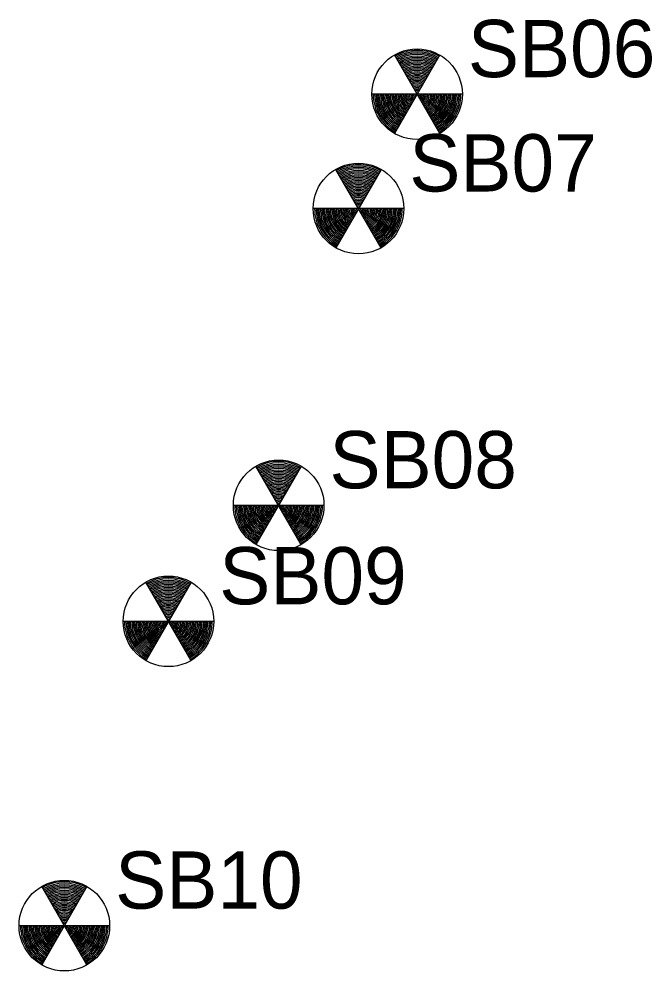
# Model space of a CAD drawing. Extents: x 557444 to 557718, y 506539 to 506965.
# Drawn here: x 557443.9 to 557488.1, y 506539.5 to 506606 of the extents above; entities that cross this region are included whole.
import ezdxf

# ---------------------------------------------------------------- set-up
doc = ezdxf.new("R2010")
doc.units = 0
doc.layers.add('Exist Roads EOP Cogo Point CELL', color=7, linetype='Continuous')

msp = doc.modelspace()

# ---------------------------------------------------------------- linework, layer by layer
at = {"layer": 'Exist Roads EOP Cogo Point CELL'}
for p, q in [((557473.295, 506597.967), (557470.133, 506603.444)), ((557473.295, 506603.444), (557470.133, 506597.967)), ((557474.876, 506600.706), (557468.552, 506600.706)), ((557469.203, 506589.983), (557466.041, 506595.46)), ((557469.203, 506595.46), (557466.041, 506589.983)), ((557470.784, 506592.722), (557464.46, 506592.722)), ((557463.63, 506569.258), (557460.468, 506574.735)), ((557463.63, 506574.735), (557460.468, 506569.258)), ((557465.211, 506571.997), (557458.887, 506571.997)), ((557455.935, 506561.159), (557452.773, 506566.635)), ((557455.935, 506566.635), (557452.773, 506561.159)), ((557457.516, 506563.897), (557451.192, 506563.897)), ((557448.668, 506539.909), (557445.506, 506545.386)), ((557448.668, 506545.386), (557445.506, 506539.909)), ((557450.249, 506542.648), (557443.925, 506542.648))]:
    msp.add_line(p, q, dxfattribs=at)
for centre in [(557471.714, 506600.706), (557467.622, 506592.722), (557462.049, 506571.997), (557454.354, 506563.897), (557447.087, 506542.648)]:
    msp.add_circle(centre, 3.162, dxfattribs=at)
for centre, radius, start, end in [((557471.714, 506600.706), 3.062, 60, 120), ((557471.714, 506600.706), 2.962, 60, 120), ((557471.714, 506600.706), 2.862, 60, 120), ((557471.714, 506600.706), 2.762, 60, 120), ((557471.714, 506600.706), 2.662, 60, 120), ((557471.714, 506600.706), 2.562, 60, 120), ((557471.714, 506600.706), 2.462, 60, 120), ((557471.714, 506600.706), 2.362, 60, 120), ((557471.714, 506600.706), 2.262, 60, 120), ((557471.714, 506600.706), 2.162, 60, 120), ((557471.714, 506600.706), 2.062, 60, 120), ((557471.714, 506600.706), 1.962, 60, 120), ((557471.714, 506600.706), 1.862, 60, 120), ((557471.714, 506600.706), 1.762, 60, 120), ((557471.714, 506600.706), 1.662, 60, 120), ((557471.714, 506600.706), 1.562, 60, 120), ((557471.714, 506600.706), 1.462, 60, 120), ((557471.714, 506600.706), 1.362, 60, 120), ((557471.714, 506600.706), 1.262, 60, 120), ((557471.714, 506600.706), 1.162, 60, 120), ((557471.714, 506600.706), 1.062, 60, 120), ((557471.714, 506600.706), 0.962, 60, 120), ((557471.714, 506600.706), 0.862, 60, 120), ((557471.714, 506600.706), 0.762, 60, 120), ((557471.714, 506600.706), 0.662, 60, 120), ((557471.714, 506600.706), 0.562, 60, 120), ((557471.714, 506600.706), 3.062, 180, 240), ((557471.714, 506600.706), 2.962, 180, 240), ((557471.714, 506600.706), 2.862, 180, 240), ((557471.714, 506600.706), 2.762, 180, 240), ((557471.714, 506600.706), 2.662, 180, 240), ((557471.714, 506600.706), 2.562, 180, 240), ((557471.714, 506600.706), 2.462, 180, 240), ((557471.714, 506600.706), 2.362, 180, 240), ((557471.714, 506600.706), 2.262, 180, 240), ((557471.714, 506600.706), 2.162, 180, 240), ((557471.714, 506600.706), 2.062, 180, 240), ((557471.714, 506600.706), 1.962, 180, 240), ((557471.714, 506600.706), 1.862, 180, 240), ((557471.714, 506600.706), 1.762, 180, 240), ((557471.714, 506600.706), 1.662, 180, 240), ((557471.714, 506600.706), 1.562, 180, 240), ((557471.714, 506600.706), 1.462, 180, 240), ((557471.714, 506600.706), 1.362, 180, 240), ((557471.714, 506600.706), 1.262, 180, 240), ((557471.714, 506600.706), 1.162, 180, 240), ((557471.714, 506600.706), 1.062, 180, 240), ((557471.714, 506600.706), 0.962, 180, 240), ((557471.714, 506600.706), 0.862, 180, 240), ((557471.714, 506600.706), 0.762, 180, 240), ((557471.714, 506600.706), 0.662, 180, 240), ((557471.714, 506600.706), 0.562, 180, 240), ((557471.714, 506600.706), 0.462, 180, 240), ((557471.714, 506600.706), 0.362, 180, 240), ((557471.714, 506600.706), 0.262, 180, 240), ((557471.714, 506600.706), 0.462, 60, 120), ((557471.714, 506600.706), 0.362, 60, 120), ((557471.714, 506600.706), 0.162, 180, 240), ((557471.714, 506600.706), 0.262, 60, 120), ((557471.714, 506600.706), 0.162, 60, 120), ((557471.714, 506600.706), 0.162, 300, 0), ((557471.714, 506600.706), 0.262, 300, 0), ((557471.714, 506600.706), 0.362, 300, 0), ((557471.714, 506600.706), 0.462, 300, 0), ((557471.714, 506600.706), 0.562, 300, 360), ((557471.714, 506600.706), 0.662, 300, 0), ((557471.714, 506600.706), 0.762, 300, 360), ((557471.714, 506600.706), 0.862, 300, 0), ((557471.714, 506600.706), 0.962, 300, 0), ((557471.714, 506600.706), 1.062, 300, 0), ((557471.714, 506600.706), 1.162, 300, 0), ((557471.714, 506600.706), 1.262, 300, 0), ((557471.714, 506600.706), 1.362, 300, 0), ((557471.714, 506600.706), 1.462, 300, 0), ((557471.714, 506600.706), 1.562, 300, 0), ((557471.714, 506600.706), 1.662, 300, 0), ((557471.714, 506600.706), 1.762, 300, 0), ((557471.714, 506600.706), 1.862, 300, 0), ((557471.714, 506600.706), 1.962, 300, 0), ((557471.714, 506600.706), 2.062, 300, 360), ((557471.714, 506600.706), 2.162, 300, 0), ((557471.714, 506600.706), 2.262, 300, 0), ((557471.714, 506600.706), 2.362, 300, 0), ((557471.714, 506600.706), 2.462, 300, 0), ((557471.714, 506600.706), 2.562, 300, 0), ((557471.714, 506600.706), 2.662, 300, 0), ((557471.714, 506600.706), 2.762, 300, 360), ((557471.714, 506600.706), 2.862, 300, 0), ((557471.714, 506600.706), 2.962, 300, 0), ((557471.714, 506600.706), 3.062, 300, 0), ((557467.622, 506592.722), 3.062, 60, 120), ((557467.622, 506592.722), 2.962, 60, 120), ((557467.622, 506592.722), 2.862, 60, 120), ((557467.622, 506592.722), 2.762, 60, 120), ((557467.622, 506592.722), 2.662, 60, 120), ((557467.622, 506592.722), 2.562, 60, 120), ((557467.622, 506592.722), 2.462, 60, 120), ((557467.622, 506592.722), 2.362, 60, 120), ((557467.622, 506592.722), 2.262, 60, 120), ((557467.622, 506592.722), 2.162, 60, 120), ((557467.622, 506592.722), 2.062, 60, 120), ((557467.622, 506592.722), 1.962, 60, 120), ((557467.622, 506592.722), 1.862, 60, 120), ((557467.622, 506592.722), 1.762, 60, 120), ((557467.622, 506592.722), 1.662, 60, 120), ((557467.622, 506592.722), 1.562, 60, 120), ((557467.622, 506592.722), 1.462, 60, 120), ((557467.622, 506592.722), 1.362, 60, 120), ((557467.622, 506592.722), 1.262, 60, 120), ((557467.622, 506592.722), 1.162, 60, 120), ((557467.622, 506592.722), 1.062, 60, 120), ((557467.622, 506592.722), 0.962, 60, 120), ((557467.622, 506592.722), 0.862, 60, 120), ((557467.622, 506592.722), 0.762, 60, 120), ((557467.622, 506592.722), 0.662, 60, 120), ((557467.622, 506592.722), 0.562, 60, 120), ((557467.622, 506592.722), 3.062, 180, 240), ((557467.622, 506592.722), 2.962, 180, 240), ((557467.622, 506592.722), 2.862, 180, 240), ((557467.622, 506592.722), 2.762, 180, 240), ((557467.622, 506592.722), 2.662, 180, 240), ((557467.622, 506592.722), 2.562, 180, 240), ((557467.622, 506592.722), 2.462, 180, 240), ((557467.622, 506592.722), 2.362, 180, 240), ((557467.622, 506592.722), 2.262, 180, 240), ((557467.622, 506592.722), 2.162, 180, 240), ((557467.622, 506592.722), 2.062, 180, 240), ((557467.622, 506592.722), 1.962, 180, 240), ((557467.622, 506592.722), 1.862, 180, 240), ((557467.622, 506592.722), 1.762, 180, 240), ((557467.622, 506592.722), 1.662, 180, 240), ((557467.622, 506592.722), 1.562, 180, 240), ((557467.622, 506592.722), 1.462, 180, 240), ((557467.622, 506592.722), 1.362, 180, 240), ((557467.622, 506592.722), 1.262, 180, 240), ((557467.622, 506592.722), 1.162, 180, 240), ((557467.622, 506592.722), 1.062, 180, 240), ((557467.622, 506592.722), 0.962, 180, 240), ((557467.622, 506592.722), 0.862, 180, 240), ((557467.622, 506592.722), 0.762, 180, 240), ((557467.622, 506592.722), 0.662, 180, 240), ((557467.622, 506592.722), 0.562, 180, 240), ((557467.622, 506592.722), 0.462, 180, 240), ((557467.622, 506592.722), 0.362, 180, 240), ((557467.622, 506592.722), 0.262, 180, 240), ((557467.622, 506592.722), 0.462, 60, 120), ((557467.622, 506592.722), 0.362, 60, 120), ((557467.622, 506592.722), 0.162, 180, 240), ((557467.622, 506592.722), 0.262, 60, 120), ((557467.622, 506592.722), 0.162, 60, 120), ((557467.622, 506592.722), 0.162, 300, 0), ((557467.622, 506592.722), 0.262, 300, 0), ((557467.622, 506592.722), 0.362, 300, 0), ((557467.622, 506592.722), 0.462, 300, 0), ((557467.622, 506592.722), 0.562, 300, 360), ((557467.622, 506592.722), 0.662, 300, 0), ((557467.622, 506592.722), 0.762, 300, 360), ((557467.622, 506592.722), 0.862, 300, 0), ((557467.622, 506592.722), 0.962, 300, 0), ((557467.622, 506592.722), 1.062, 300, 0), ((557467.622, 506592.722), 1.162, 300, 0), ((557467.622, 506592.722), 1.262, 300, 0), ((557467.622, 506592.722), 1.362, 300, 0), ((557467.622, 506592.722), 1.462, 300, 0), ((557467.622, 506592.722), 1.562, 300, 0), ((557467.622, 506592.722), 1.662, 300, 0), ((557467.622, 506592.722), 1.762, 300, 0), ((557467.622, 506592.722), 1.862, 300, 0), ((557467.622, 506592.722), 1.962, 300, 0), ((557467.622, 506592.722), 2.062, 300, 360), ((557467.622, 506592.722), 2.162, 300, 0), ((557467.622, 506592.722), 2.262, 300, 0), ((557467.622, 506592.722), 2.362, 300, 0), ((557467.622, 506592.722), 2.462, 300, 0), ((557467.622, 506592.722), 2.562, 300, 0), ((557467.622, 506592.722), 2.662, 300, 0), ((557467.622, 506592.722), 2.762, 300, 360), ((557467.622, 506592.722), 2.862, 300, 0), ((557467.622, 506592.722), 2.962, 300, 0), ((557467.622, 506592.722), 3.062, 300, 0), ((557462.049, 506571.997), 3.062, 60, 120), ((557462.049, 506571.997), 2.962, 60, 120), ((557462.049, 506571.997), 2.862, 60, 120), ((557462.049, 506571.997), 2.762, 60, 120), ((557462.049, 506571.997), 2.662, 60, 120), ((557462.049, 506571.997), 2.562, 60, 120), ((557462.049, 506571.997), 2.462, 60, 120), ((557462.049, 506571.997), 2.362, 60, 120), ((557462.049, 506571.997), 2.262, 60, 120), ((557462.049, 506571.997), 2.162, 60, 120), ((557462.049, 506571.997), 2.062, 60, 120), ((557462.049, 506571.997), 1.962, 60, 120), ((557462.049, 506571.997), 1.862, 60, 120), ((557462.049, 506571.997), 1.762, 60, 120), ((557462.049, 506571.997), 1.662, 60, 120), ((557462.049, 506571.997), 1.562, 60, 120), ((557462.049, 506571.997), 1.462, 60, 120), ((557462.049, 506571.997), 1.362, 60, 120), ((557462.049, 506571.997), 1.262, 60, 120), ((557462.049, 506571.997), 1.162, 60, 120), ((557462.049, 506571.997), 1.062, 60, 120), ((557462.049, 506571.997), 0.962, 60, 120), ((557462.049, 506571.997), 0.862, 60, 120), ((557462.049, 506571.997), 0.762, 60, 120), ((557462.049, 506571.997), 0.662, 60, 120), ((557462.049, 506571.997), 3.062, 180, 240), ((557462.049, 506571.997), 2.962, 180, 240), ((557462.049, 506571.997), 2.862, 180, 240), ((557462.049, 506571.997), 2.762, 180, 240), ((557462.049, 506571.997), 2.662, 180, 240), ((557462.049, 506571.997), 2.562, 180, 240), ((557462.049, 506571.997), 2.462, 180, 240), ((557462.049, 506571.997), 2.362, 180, 240), ((557462.049, 506571.997), 2.262, 180, 240), ((557462.049, 506571.997), 2.162, 180, 240), ((557462.049, 506571.997), 2.062, 180, 240), ((557462.049, 506571.997), 1.962, 180, 240), ((557462.049, 506571.997), 1.862, 180, 240), ((557462.049, 506571.997), 1.762, 180, 240), ((557462.049, 506571.997), 1.662, 180, 240), ((557462.049, 506571.997), 1.562, 180, 240), ((557462.049, 506571.997), 1.462, 180, 240), ((557462.049, 506571.997), 1.362, 180, 240), ((557462.049, 506571.997), 1.262, 180, 240), ((557462.049, 506571.997), 1.162, 180, 240), ((557462.049, 506571.997), 1.062, 180, 240), ((557462.049, 506571.997), 0.962, 180, 240), ((557462.049, 506571.997), 0.862, 180, 240), ((557462.049, 506571.997), 0.762, 180, 240), ((557462.049, 506571.997), 0.662, 180, 240), ((557462.049, 506571.997), 0.562, 180, 240), ((557462.049, 506571.997), 0.462, 180, 240), ((557462.049, 506571.997), 0.362, 180, 240), ((557462.049, 506571.997), 0.562, 60, 120), ((557462.049, 506571.997), 0.262, 180, 240), ((557462.049, 506571.997), 0.462, 60, 120), ((557462.049, 506571.997), 0.362, 60, 120), ((557462.049, 506571.997), 0.162, 180, 240), ((557462.049, 506571.997), 0.262, 60, 120), ((557462.049, 506571.997), 0.162, 60, 120), ((557462.049, 506571.997), 0.162, 300, 0), ((557462.049, 506571.997), 0.262, 300, 0), ((557462.049, 506571.997), 0.362, 300, 0), ((557462.049, 506571.997), 0.462, 300, 0), ((557462.049, 506571.997), 0.562, 300, 360), ((557462.049, 506571.997), 0.662, 300, 0), ((557462.049, 506571.997), 0.762, 300, 360), ((557462.049, 506571.997), 0.862, 300, 0), ((557462.049, 506571.997), 0.962, 300, 0), ((557462.049, 506571.997), 1.062, 300, 0), ((557462.049, 506571.997), 1.162, 300, 0), ((557462.049, 506571.997), 1.262, 300, 0), ((557462.049, 506571.997), 1.362, 300, 0), ((557462.049, 506571.997), 1.462, 300, 0), ((557462.049, 506571.997), 1.562, 300, 0), ((557462.049, 506571.997), 1.662, 300, 0), ((557462.049, 506571.997), 1.762, 300, 0), ((557462.049, 506571.997), 1.862, 300, 0), ((557462.049, 506571.997), 1.962, 300, 0), ((557462.049, 506571.997), 2.062, 300, 360), ((557462.049, 506571.997), 2.162, 300, 0), ((557462.049, 506571.997), 2.262, 300, 0), ((557462.049, 506571.997), 2.362, 300, 0), ((557462.049, 506571.997), 2.462, 300, 0), ((557462.049, 506571.997), 2.562, 300, 0), ((557462.049, 506571.997), 2.662, 300, 0), ((557462.049, 506571.997), 2.762, 300, 360), ((557462.049, 506571.997), 2.862, 300, 0), ((557462.049, 506571.997), 2.962, 300, 0), ((557462.049, 506571.997), 3.062, 300, 0), ((557454.354, 506563.897), 3.062, 60, 120), ((557454.354, 506563.897), 2.962, 60, 120), ((557454.354, 506563.897), 2.862, 60, 120), ((557454.354, 506563.897), 2.762, 60, 120), ((557454.354, 506563.897), 2.662, 60, 120), ((557454.354, 506563.897), 2.562, 60, 120), ((557454.354, 506563.897), 2.462, 60, 120), ((557454.354, 506563.897), 2.362, 60, 120), ((557454.354, 506563.897), 2.262, 60, 120), ((557454.354, 506563.897), 2.162, 60, 120), ((557454.354, 506563.897), 2.062, 60, 120), ((557454.354, 506563.897), 1.962, 60, 120), ((557454.354, 506563.897), 1.862, 60, 120), ((557454.354, 506563.897), 1.762, 60, 120), ((557454.354, 506563.897), 1.662, 60, 120), ((557454.354, 506563.897), 1.562, 60, 120), ((557454.354, 506563.897), 1.462, 60, 120), ((557454.354, 506563.897), 1.362, 60, 120), ((557454.354, 506563.897), 1.262, 60, 120), ((557454.354, 506563.897), 1.162, 60, 120), ((557454.354, 506563.897), 1.062, 60, 120), ((557454.354, 506563.897), 0.962, 60, 120), ((557454.354, 506563.897), 0.862, 60, 120), ((557454.354, 506563.897), 0.762, 60, 120), ((557454.354, 506563.897), 0.662, 60, 120), ((557454.354, 506563.897), 0.562, 60, 120), ((557454.354, 506563.897), 0.462, 60, 120), ((557454.354, 506563.897), 0.362, 60, 120), ((557454.354, 506563.897), 0.262, 60, 120), ((557454.354, 506563.897), 0.162, 60, 120), ((557454.354, 506563.897), 3.062, 180, 240), ((557454.354, 506563.897), 2.962, 180, 240), ((557454.354, 506563.897), 2.862, 180, 240), ((557454.354, 506563.897), 2.762, 180, 240), ((557454.354, 506563.897), 2.662, 180, 240), ((557454.354, 506563.897), 2.562, 180, 240), ((557454.354, 506563.897), 2.462, 180, 240), ((557454.354, 506563.897), 2.362, 180, 240), ((557454.354, 506563.897), 2.262, 180, 240), ((557454.354, 506563.897), 2.162, 180, 240), ((557454.354, 506563.897), 2.062, 180, 240), ((557454.354, 506563.897), 1.962, 180, 240), ((557454.354, 506563.897), 1.862, 180, 240), ((557454.354, 506563.897), 1.762, 180, 240), ((557454.354, 506563.897), 1.662, 180, 240), ((557454.354, 506563.897), 1.562, 180, 240), ((557454.354, 506563.897), 1.462, 180, 240), ((557454.354, 506563.897), 1.362, 180, 240), ((557454.354, 506563.897), 1.262, 180, 240), ((557454.354, 506563.897), 1.162, 180, 240), ((557454.354, 506563.897), 1.062, 180, 240), ((557454.354, 506563.897), 0.962, 180, 240), ((557454.354, 506563.897), 0.862, 180, 240), ((557454.354, 506563.897), 0.762, 180, 240), ((557454.354, 506563.897), 0.662, 180, 240), ((557454.354, 506563.897), 0.562, 180, 240), ((557454.354, 506563.897), 0.462, 180, 240), ((557454.354, 506563.897), 0.362, 180, 240), ((557454.354, 506563.897), 0.262, 180, 240), ((557454.354, 506563.897), 0.162, 180, 240), ((557454.354, 506563.897), 0.162, 300, 0), ((557454.354, 506563.897), 0.262, 300, 0), ((557454.354, 506563.897), 0.362, 300, 0), ((557454.354, 506563.897), 0.462, 300, 0), ((557454.354, 506563.897), 0.562, 300, 360), ((557454.354, 506563.897), 0.662, 300, 0), ((557454.354, 506563.897), 0.762, 300, 360), ((557454.354, 506563.897), 0.862, 300, 0), ((557454.354, 506563.897), 0.962, 300, 0), ((557454.354, 506563.897), 1.062, 300, 0), ((557454.354, 506563.897), 1.162, 300, 0), ((557454.354, 506563.897), 1.262, 300, 0), ((557454.354, 506563.897), 1.362, 300, 0), ((557454.354, 506563.897), 1.462, 300, 0), ((557454.354, 506563.897), 1.562, 300, 0), ((557454.354, 506563.897), 1.662, 300, 0), ((557454.354, 506563.897), 1.762, 300, 0), ((557454.354, 506563.897), 1.862, 300, 0), ((557454.354, 506563.897), 1.962, 300, 0), ((557454.354, 506563.897), 2.062, 300, 360), ((557454.354, 506563.897), 2.162, 300, 0), ((557454.354, 506563.897), 2.262, 300, 0), ((557454.354, 506563.897), 2.362, 300, 0), ((557454.354, 506563.897), 2.462, 300, 0), ((557454.354, 506563.897), 2.562, 300, 0), ((557454.354, 506563.897), 2.662, 300, 0), ((557454.354, 506563.897), 2.762, 300, 360), ((557454.354, 506563.897), 2.862, 300, 0), ((557454.354, 506563.897), 2.962, 300, 0), ((557454.354, 506563.897), 3.062, 300, 0), ((557447.087, 506542.648), 3.062, 60, 120), ((557447.087, 506542.648), 2.962, 60, 120), ((557447.087, 506542.648), 2.862, 60, 120), ((557447.087, 506542.648), 2.762, 60, 120), ((557447.087, 506542.648), 2.662, 60, 120), ((557447.087, 506542.648), 2.562, 60, 120), ((557447.087, 506542.648), 2.462, 60, 120), ((557447.087, 506542.648), 2.362, 60, 120), ((557447.087, 506542.648), 2.262, 60, 120), ((557447.087, 506542.648), 2.162, 60, 120), ((557447.087, 506542.648), 2.062, 60, 120), ((557447.087, 506542.648), 1.962, 60, 120), ((557447.087, 506542.648), 1.862, 60, 120), ((557447.087, 506542.648), 1.762, 60, 120), ((557447.087, 506542.648), 1.662, 60, 120), ((557447.087, 506542.648), 1.562, 60, 120), ((557447.087, 506542.648), 1.462, 60, 120), ((557447.087, 506542.648), 1.362, 60, 120), ((557447.087, 506542.648), 1.262, 60, 120), ((557447.087, 506542.648), 1.162, 60, 120), ((557447.087, 506542.648), 1.062, 60, 120), ((557447.087, 506542.648), 0.962, 60, 120), ((557447.087, 506542.648), 0.862, 60, 120), ((557447.087, 506542.648), 0.762, 60, 120), ((557447.087, 506542.648), 0.662, 60, 120), ((557447.087, 506542.648), 0.562, 60, 120), ((557447.087, 506542.648), 0.462, 60, 120), ((557447.087, 506542.648), 0.362, 60, 120), ((557447.087, 506542.648), 0.262, 60, 120), ((557447.087, 506542.648), 0.162, 60, 120), ((557447.087, 506542.648), 3.062, 180, 240), ((557447.087, 506542.648), 2.962, 180, 240), ((557447.087, 506542.648), 2.862, 180, 240), ((557447.087, 506542.648), 2.762, 180, 240), ((557447.087, 506542.648), 2.662, 180, 240), ((557447.087, 506542.648), 2.562, 180, 240), ((557447.087, 506542.648), 2.462, 180, 240), ((557447.087, 506542.648), 2.362, 180, 240), ((557447.087, 506542.648), 2.262, 180, 240), ((557447.087, 506542.648), 2.162, 180, 240), ((557447.087, 506542.648), 2.062, 180, 240), ((557447.087, 506542.648), 1.962, 180, 240), ((557447.087, 506542.648), 1.862, 180, 240), ((557447.087, 506542.648), 1.762, 180, 240), ((557447.087, 506542.648), 1.662, 180, 240), ((557447.087, 506542.648), 1.562, 180, 240), ((557447.087, 506542.648), 1.462, 180, 240), ((557447.087, 506542.648), 1.362, 180, 240), ((557447.087, 506542.648), 1.262, 180, 240), ((557447.087, 506542.648), 1.162, 180, 240), ((557447.087, 506542.648), 1.062, 180, 240), ((557447.087, 506542.648), 0.962, 180, 240), ((557447.087, 506542.648), 0.862, 180, 240), ((557447.087, 506542.648), 0.762, 180, 240), ((557447.087, 506542.648), 0.662, 180, 240), ((557447.087, 506542.648), 0.562, 180, 240), ((557447.087, 506542.648), 0.462, 180, 240), ((557447.087, 506542.648), 0.362, 180, 240), ((557447.087, 506542.648), 0.262, 180, 240), ((557447.087, 506542.648), 0.162, 180, 240), ((557447.087, 506542.648), 0.162, 300, 0), ((557447.087, 506542.648), 0.262, 300, 0), ((557447.087, 506542.648), 0.362, 300, 0), ((557447.087, 506542.648), 0.462, 300, 0), ((557447.087, 506542.648), 0.562, 300, 360), ((557447.087, 506542.648), 0.662, 300, 0), ((557447.087, 506542.648), 0.762, 300, 360), ((557447.087, 506542.648), 0.862, 300, 0), ((557447.087, 506542.648), 0.962, 300, 0), ((557447.087, 506542.648), 1.062, 300, 0), ((557447.087, 506542.648), 1.162, 300, 0), ((557447.087, 506542.648), 1.262, 300, 0), ((557447.087, 506542.648), 1.362, 300, 0), ((557447.087, 506542.648), 1.462, 300, 0), ((557447.087, 506542.648), 1.562, 300, 0), ((557447.087, 506542.648), 1.662, 300, 0), ((557447.087, 506542.648), 1.762, 300, 0), ((557447.087, 506542.648), 1.862, 300, 0), ((557447.087, 506542.648), 1.962, 300, 0), ((557447.087, 506542.648), 2.062, 300, 360), ((557447.087, 506542.648), 2.162, 300, 0), ((557447.087, 506542.648), 2.262, 300, 0), ((557447.087, 506542.648), 2.362, 300, 0), ((557447.087, 506542.648), 2.462, 300, 0), ((557447.087, 506542.648), 2.562, 300, 0), ((557447.087, 506542.648), 2.662, 300, 0), ((557447.087, 506542.648), 2.762, 300, 360), ((557447.087, 506542.648), 2.862, 300, 0), ((557447.087, 506542.648), 2.962, 300, 0), ((557447.087, 506542.648), 3.062, 300, 0)]:
    msp.add_arc(centre, radius, start, end, dxfattribs=at)

# ---------------------------------------------------------------- texts
for s, p in [('SB06', (557475.263, 506601.895)), ('SB07', (557471.171, 506593.911)), ('SB08', (557465.597, 506573.186)), ('SB09', (557457.902, 506565.086)), ('SB10', (557450.635, 506543.837))]:
    msp.add_text(s, height=4, dxfattribs=at).set_placement(p)

doc.saveas('drawing.dxf')
